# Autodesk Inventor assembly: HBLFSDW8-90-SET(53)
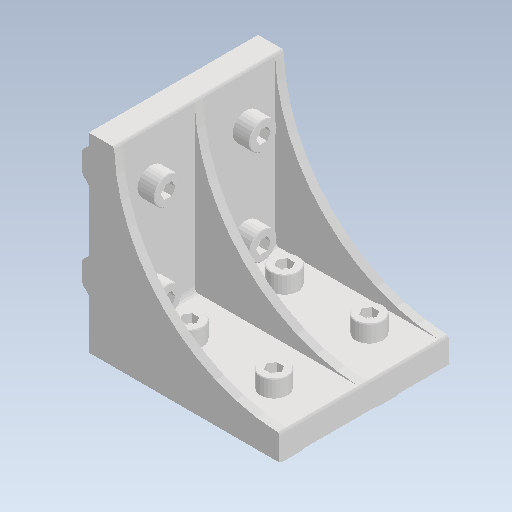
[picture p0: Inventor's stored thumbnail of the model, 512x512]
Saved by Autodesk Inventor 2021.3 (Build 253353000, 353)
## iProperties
Created: 2022-02
Part Number: HBLFSDW8-90-SET(53)
Document SubType Name: Assembly
Designer: kengo
Author: kengo
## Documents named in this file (4)
- C:\Users\kengo\Documents\S2S_frame\SDC345\frame_misumi_ver12\HBLFSDW8-90-SET(53).iam
- C:\Users\kengo\Documents\S2S_frame\SDC345\frame_misumi_ver12\HBLFSDW8-90.ipt
- C:\Users\kengo\Documents\S2S_frame\SDC345\frame_misumi_ver12\HNTT8-8.ipt
- C:\Users\kengo\Documents\S2S_frame\SDC345\frame_misumi_ver12\SCB8-22.ipt
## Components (17 placed, 3 different names)
1. HBLFSDW8-90
2. HNTT8-8
3. SCB8-22
4. HNTT8-8:1
5. SCB8-22:1
6. HNTT8-8:2
7. SCB8-22:2
8. HNTT8-8:3
9. SCB8-22:3
10. HNTT8-8:4
11. SCB8-22:4
12. HNTT8-8:5
13. SCB8-22:5
14. HNTT8-8:6
15. SCB8-22:6
16. HNTT8-8:7
17. SCB8-22:7
